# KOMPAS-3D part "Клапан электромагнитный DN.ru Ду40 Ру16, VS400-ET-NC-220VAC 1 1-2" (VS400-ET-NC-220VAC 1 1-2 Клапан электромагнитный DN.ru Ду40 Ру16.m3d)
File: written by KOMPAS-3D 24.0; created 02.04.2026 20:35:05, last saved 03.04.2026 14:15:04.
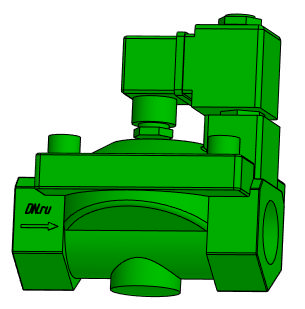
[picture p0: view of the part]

Document properties: Автор: artio; Полное имя файла: C:\Users\artio\OneDrive\Рабочий стол\Клапан электромагнитный DN.ru\VS400-ET-NC-220VAC 1 1-2 Клапан электромагнитный DN.ru Ду40 Ру16.m3d

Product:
- Body: Тело 1  | qty 1
    Масса: 4.144257
- Part/product: Клапан электромагнитный DN.ru Ду40 Ру16  | designation VS400-ET-NC-220VAC 1 1-2
    Масса: 2.321
    Раздел спецификации: Прочие изделия
    Примечание: D130-04695
    additional columns: ef56311e-7521-43dc-8291-0e6108b3d81d; VS400-ET-NC-220VAC 1 1-2; artio; c; Шероховатость не задана; Да

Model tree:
1. Операция без истории:1

Expressions: VS400-ET-NC-220VAC 1 1-2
